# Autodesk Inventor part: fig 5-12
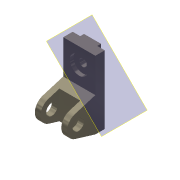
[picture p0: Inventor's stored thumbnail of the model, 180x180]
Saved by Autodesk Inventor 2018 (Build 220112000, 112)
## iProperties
Shininess: 65.0
Angle Display Precision: 2
Document Length Units: 11269
Document Angle Units: 11279
Document Time Units: 11290
Document Mass Units: 11283
Document Length Units Precision: 3
Document Angle Units Precision: 2
Compacted: False
Created: 2001-11
Part Number: fig 5-12
Document SubType Name: Modeling
Designer: Renu Muthoo
Density: 1 g/cm^3
Material: Generic
Appearance: Metal-Titanium (Polished)
Density: 0.0
Volumn: 0.0
Area: 0.0
PropertySet Name: Model Information
Control State: 0
Master: False
Checked Out: False
Author: Renu Muthoo
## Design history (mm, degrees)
node "Sketch1"
sketch "Sketch2"
  geometry: L1 (33.257, 104.664)-(33.257, -75.336); L2 (33.257, -75.336)-(8.257, -75.336); L3 (8.257, -75.336)-(-45.451, -59.045); L4 (-45.451, -1.628)-(8.257, 14.664); L5 (8.257, 14.664)-(8.257, 104.664); L6 (8.257, 104.664)-(33.257, 104.664); C1 r 15 at (-36.743, -30.336); A1 r 30 centre (-36.743, -30.336) between (-45.451, -1.628) and (-45.451, -59.045)
  constraints: 12 end point, 2 centre point, 2 equal length, 2 parallel, 2 point on circle, 2 tangent, 1 coincident, 1 perpendicular, 1 vertical
  dimensions: "d0" = 180 distance of L1.start L1.end; "d1" = 30 radius of A1; "d2" = 25 distance of L5.end L1.start; "d3" = 45 distance from line of L2 A1.centre; "d4" = 70 distance from line of L1 A1.centre; "d5" = 30 diameter of C1
extrude "Extrusion1" new body sketch "Sketch2" distance "d6" = 85; taper "d7" = 0 deg
workplane "Work Plane1"
sketch "Sketch3"
  geometry: L1 (15, 62.364)-(70, 62.364); L2 (70, 62.364)-(70, -52.386); L3 (70, -52.386)-(15, -52.386); L4 (15, -52.386)-(15, 62.364); L5 (0, -45)-(0, -28.708) reference
  constraints: 8 end point, 2 parallel, 1 horizontal, 1 perpendicular
  dimensions: "d8" = 55 distance of L1.start L1.end; "d9" = 15 distance between parallel lines of L5 L4
extrude "Extrusion2" cut sketch "Sketch3" distance "d10" = 50; taper "d11" = 0 deg
sketch "Sketch4"
  geometry: L1 (0, 25)-(85, 25) reference; L2 (0, 0)-(0, 25) reference; L3 (20, 25)-(65, 25); L4 (65, 25)-(65, 35); L5 (65, 35)-(20, 35); L6 (20, 35)-(20, 25)
  constraints: 8 end point, 2 parallel, 1 horizontal, 1 perpendicular, 1 point on line
  dimensions: "d12" = 45 distance of L4.end L5.end; "d13" = 10 distance of L3.end L4.end; "d14" = 20 distance between parallel lines of L2 L6
extrude "Extrusion3" join sketch "Sketch4" stored distance "d15" = 50; taper "d16" = 0 deg
sketch "Sketch5"
  geometry: L1 (85, 0)-(85, 90) reference; L2 (0, 90)-(85, 90) reference; 1 further point
  dimensions: "d17" = 42 distance from line of L2 point (42.5, 48); "d18" = 42.5 distance from line of L1 point (42.5, 48)
hole "Hole1" sketch "Sketch5" at (42.5, 48) diameter "d19" = 20; stored, may be unused: countersink angle "d23" = 82 deg, drill point angle "d25" = 118 deg; dims "d20" = 6, "d21" = 50, "d22" = 10, "d24" = 8
workplane "Work Plane8"
body "Solid1"
other parameters: "d28" = 135 deg
